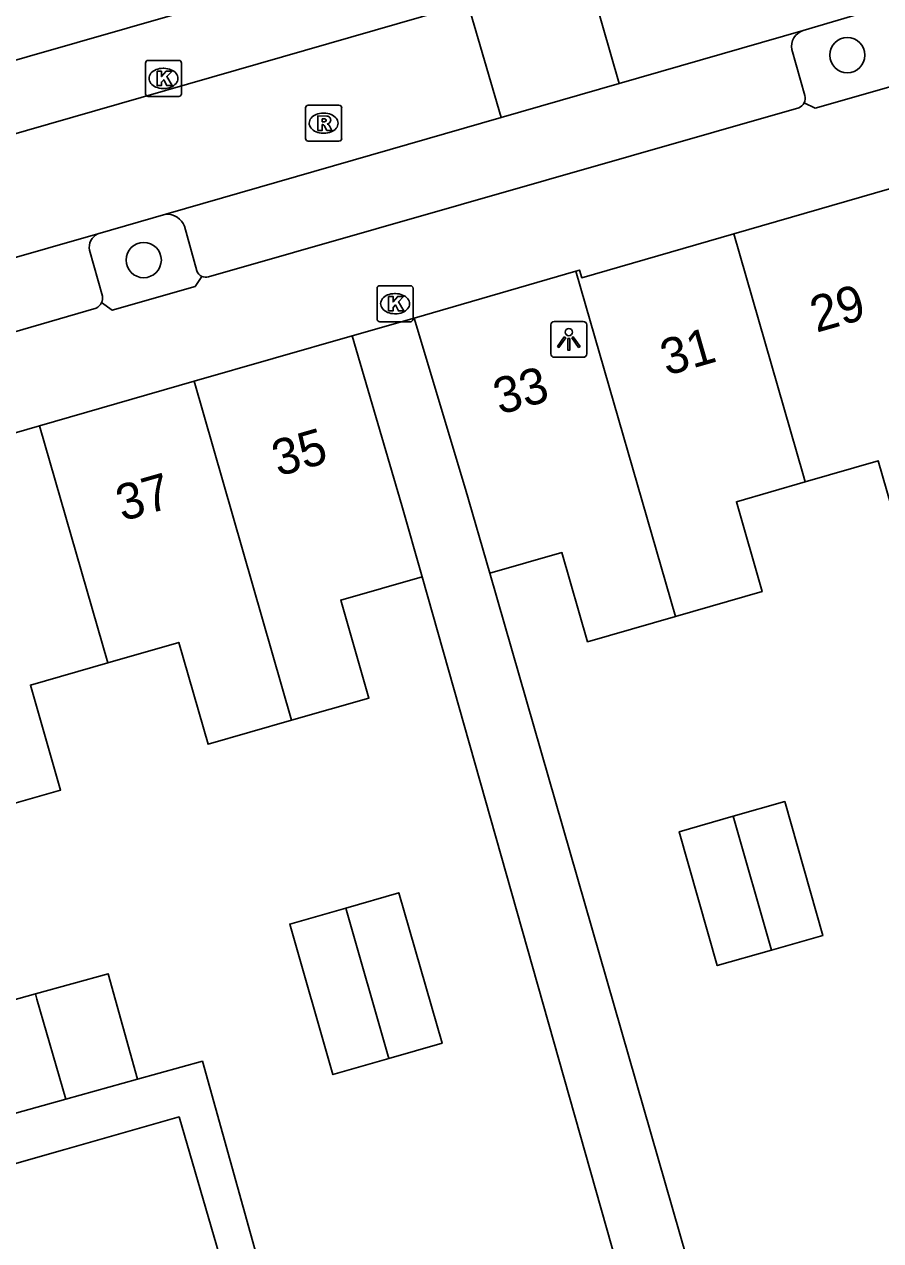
# Model space of a CAD drawing. Extents: x 159718 to 160783, y 383290 to 384030.
# Drawn here: x 160303.99 to 160327.77, y 383562.46 to 383596.25 of the extents above; entities that cross this region are included whole.
import ezdxf

# ---------------------------------------------------------------- set-up
doc = ezdxf.new("R2010")
doc.units = 0
for name, color, linetype in [('IMGEO_Boom', 7, 'Continuous'), ('IMGEO_Kolk', 7, 'Continuous'), ('IMGEO_Lichtpunt', 7, 'Continuous'), ('IMGEO_Pand', 7, 'Continuous'), ('IMGEO_Pand_nummerreeks', 7, 'Continuous'), ('IMGEO_Parkeervlak_open', 7, 'Continuous'), ('IMGEO_Rijbaan_lokaal_open', 7, 'Continuous'), ('IMGEO_Rioolput', 7, 'Continuous'), ('IMGEO_Voetpad_open', 7, 'Continuous')]:
    doc.layers.add(name, color=color, linetype=linetype)

msp = doc.modelspace()

# ---------------------------------------------------------------- linework, layer by layer
at = {"layer": 'IMGEO_Boom'}
for centre in [(160326.846, 383595.394), (160307.303, 383589.7)]:
    msp.add_circle(centre, 0.489, dxfattribs=at)
at = {"layer": 'IMGEO_Kolk'}
for p, q in [((160307.351, 383594.322), (160307.351, 383595.174)), ((160307.426, 383595.248), (160308.278, 383595.248)), ((160307.839, 383595.028), (160307.864, 383595.028)), ((160308.352, 383595.174), (160308.352, 383594.322)), ((160307.862, 383594.468), (160307.837, 383594.468)), ((160308.278, 383594.248), (160307.426, 383594.248)), ((160313.783, 383588.063), (160313.783, 383588.915)), ((160313.858, 383588.989), (160314.71, 383588.989)), ((160314.784, 383588.915), (160314.784, 383588.063)), ((160314.271, 383588.769), (160314.296, 383588.769)), ((160314.71, 383587.989), (160313.858, 383587.989)), ((160314.294, 383588.209), (160314.269, 383588.209))]:
    msp.add_line(p, q, dxfattribs=at)
for points in [[(160307.351, 383594.322), (160307.351, 383595.174)], [(160307.426, 383595.248), (160308.278, 383595.248)], [(160308.352, 383595.174), (160308.352, 383594.322)], [(160307.672, 383594.948), (160307.795, 383594.948), (160307.795, 383594.797), (160307.925, 383594.948), (160308.089, 383594.948), (160307.943, 383594.797), (160308.096, 383594.548), (160307.944, 383594.548), (160307.859, 383594.712), (160307.795, 383594.645), (160307.795, 383594.548), (160307.672, 383594.548), (160307.672, 383594.948)], [(160308.278, 383594.248), (160307.426, 383594.248)], [(160313.783, 383588.063), (160313.783, 383588.915)], [(160313.858, 383588.989), (160314.71, 383588.989)], [(160314.784, 383588.915), (160314.784, 383588.063)], [(160314.104, 383588.689), (160314.227, 383588.689), (160314.227, 383588.538), (160314.357, 383588.689), (160314.521, 383588.689), (160314.375, 383588.538), (160314.528, 383588.289), (160314.376, 383588.289), (160314.291, 383588.453), (160314.227, 383588.386), (160314.227, 383588.289), (160314.104, 383588.289), (160314.104, 383588.689)], [(160314.71, 383587.989), (160313.858, 383587.989)]]:
    msp.add_lwpolyline(points, dxfattribs=at)
for centre, start, end in [((160307.428, 383595.172), 91.552, 178.448), ((160307.428, 383595.172), 91.552, 178.448), ((160308.276, 383595.172), 1.552, 88.448), ((160308.276, 383595.172), 1.552, 88.448), ((160307.428, 383594.324), 181.552, 268.448), ((160307.428, 383594.324), 181.552, 268.448), ((160308.276, 383594.324), 271.552, 358.448), ((160308.276, 383594.324), 271.552, 358.448), ((160313.86, 383588.913), 91.552, 178.448), ((160313.86, 383588.913), 91.552, 178.448), ((160314.708, 383588.913), 1.552, 88.448), ((160314.708, 383588.913), 1.552, 88.448), ((160313.86, 383588.065), 181.552, 268.448), ((160313.86, 383588.065), 181.552, 268.448), ((160314.708, 383588.065), 271.552, 358.448), ((160314.708, 383588.065), 271.552, 358.448)]:
    msp.add_arc(centre, 0.0765, start, end, dxfattribs=at)
for centre, major_axis, ratio, start_param, end_param in [((160307.838, 383594.748), (-0.387, 0.002), 0.722429, 4.712389, 7.853982), ((160307.863, 383594.748), (-0.39, 0.002), 0.717154, 1.570796, 4.712389), ((160314.27, 383588.489), (-0.387, 0.002), 0.722429, 4.712389, 7.853982), ((160314.295, 383588.489), (-0.39, 0.002), 0.717154, 1.570796, 4.712389)]:
    msp.add_ellipse(centre, major_axis=major_axis, ratio=ratio, start_param=start_param, end_param=end_param, dxfattribs=at)
at = {"layer": 'IMGEO_Lichtpunt'}
for p, q in [((160318.61, 383587.902), (160318.61, 383587.095)), ((160318.61, 383587.902), (160318.61, 383587.095)), ((160319.512, 383587.997), (160318.704, 383587.997)), ((160319.512, 383587.997), (160318.704, 383587.997)), ((160319.606, 383587.095), (160319.606, 383587.902)), ((160319.606, 383587.095), (160319.606, 383587.902)), ((160318.704, 383587.001), (160319.512, 383587.001)), ((160318.704, 383587.001), (160319.512, 383587.001))]:
    msp.add_line(p, q, dxfattribs=at)
for points in [[(160318.984, 383587.566), (160319.023, 383587.538), (160318.835, 383587.276), (160318.797, 383587.303), (160318.984, 383587.566)], [(160319.196, 383587.538), (160319.234, 383587.565), (160319.421, 383587.303), (160319.382, 383587.275), (160319.196, 383587.538)], [(160319.086, 383587.518), (160319.133, 383587.518), (160319.133, 383587.196), (160319.086, 383587.196), (160319.086, 383587.518)]]:
    msp.add_lwpolyline(points, dxfattribs=at)
msp.add_circle((160319.109, 383587.7), 0.0994, dxfattribs=at)
for centre, start, end in [((160318.704, 383587.902), 90, 180), ((160318.704, 383587.902), 90, 180), ((160319.512, 383587.902), 0, 90), ((160319.512, 383587.902), 0, 90), ((160318.704, 383587.095), 180, 270), ((160318.704, 383587.095), 180, 270), ((160319.512, 383587.095), 270, 0), ((160319.512, 383587.095), 270, 360)]:
    msp.add_arc(centre, 0.0946, start, end, dxfattribs=at)
at = {"layer": 'IMGEO_Pand'}
for points in [[(160328.012, 383591.677), (160323.69, 383590.429)], [(160323.69, 383590.429), (160319.47, 383589.211), (160319.409, 383589.422), (160319.305, 383589.392)], [(160323.69, 383590.429), (160325.61, 383583.776), (160325.678, 383583.54)], [(160319.305, 383589.392), (160314.818, 383588.09)], [(160322.074, 383579.8), (160319.305, 383589.392)], [(160314.818, 383588.09), (160316.244, 383583.337), (160316.916, 383581)], [(160313.09, 383587.598), (160308.703, 383586.333)], [(160315.034, 383580.904), (160314.474, 383582.881), (160313.09, 383587.598)], [(160308.703, 383586.333), (160304.408, 383585.094)], [(160311.411, 383576.917), (160308.703, 383586.333)], [(160304.408, 383585.094), (160300.113, 383583.856)], [(160304.408, 383585.094), (160306.302, 383578.509)], [(160325.678, 383583.54), (160327.702, 383584.127), (160328.421, 383581.626), (160330.724, 383582.283)], [(160322.074, 383579.8), (160324.479, 383580.492), (160323.762, 383582.985), (160325.678, 383583.54)], [(160316.916, 383581), (160318.916, 383581.576), (160319.629, 383579.097), (160322.074, 383579.8)], [(160311.411, 383576.917), (160313.557, 383577.534), (160312.775, 383580.255), (160315.034, 383580.904)], [(160306.302, 383578.509), (160308.275, 383579.077), (160309.088, 383576.249), (160311.411, 383576.917)], [(160306.302, 383578.509), (160304.155, 383577.892), (160304.993, 383574.978), (160302.844, 383574.36)], [(160324.737, 383570.528), (160326.168, 383570.936), (160325.108, 383574.658), (160323.677, 383574.25)], [(160323.677, 383574.25), (160322.17, 383573.821), (160323.23, 383570.099), (160324.737, 383570.528)], [(160323.677, 383574.25), (160324.737, 383570.528)], [(160314.113, 383567.521), (160315.588, 383567.945), (160314.387, 383572.123), (160312.912, 383571.699)], [(160312.912, 383571.699), (160311.357, 383571.252), (160312.559, 383567.073), (160314.113, 383567.521)], [(160312.912, 383571.699), (160314.113, 383567.521)], [(160307.129, 383566.941), (160306.313, 383569.873), (160304.296, 383569.312)], [(160304.296, 383569.312), (160302.498, 383568.812), (160302.538, 383568.664), (160303.293, 383565.952)], [(160305.137, 383566.386), (160304.338, 383569.166), (160304.296, 383569.312)], [(160305.137, 383566.386), (160307.129, 383566.941)], [(160303.293, 383565.952), (160303.314, 383565.878), (160305.137, 383566.386)]]:
    msp.add_lwpolyline(points, dxfattribs=at)
at = {"layer": 'IMGEO_Parkeervlak_open'}
for points in [[(160360.615, 383611.67), (160327.739, 383602.146), (160280.384, 383588.556), (160278.661, 383588.057)], [(160325.665, 383594.27), (160325.304, 383595.549)], [(160308.437, 383590.644), (160308.776, 383589.4)], [(160306.155, 383588.702), (160305.795, 383589.974)]]:
    msp.add_lwpolyline(points, dxfattribs=at)
for centre, radius, start, end in [((160325.747, 383595.642), 0.453, 106.42, 191.8445), ((160325.407, 383594.188), 0.271, 333.2912, 17.7396), ((160307.924, 383590.417), 0.561, 23.8591, 90.4132), ((160306.206, 383590.051), 0.418, 115.3607, 190.6061), ((160309.024, 383589.487), 0.263, 199.4219, 245.0121), ((160305.822, 383588.659), 0.336, 335.2577, 7.4372)]:
    msp.add_arc(centre, radius, start, end, dxfattribs=at)
at = {"layer": 'IMGEO_Rijbaan_lokaal_open'}
for points in [[(160319.597, 383597.777), (160320.503, 383594.602)], [(160278.849, 383586.224), (160280.889, 383586.747), (160286.571, 383588.273), (160316.301, 383596.829)], [(160316.301, 383596.829), (160317.226, 383593.659)], [(160325.619, 383596.076), (160327.401, 383596.608)], [(160320.503, 383594.602), (160325.619, 383596.076)], [(160320.503, 383594.602), (160317.226, 383593.659)], [(160317.226, 383593.659), (160307.92, 383590.978)], [(160306.027, 383590.429), (160307.92, 383590.978)], [(160288.354, 383585.361), (160306.027, 383590.429)]]:
    msp.add_lwpolyline(points, dxfattribs=at)
at = {"layer": 'IMGEO_Rioolput'}
for p, q in [((160311.874, 383594.004), (160312.726, 383594.004)), ((160311.799, 383593.078), (160311.799, 383593.93)), ((160312.287, 383593.784), (160312.312, 383593.784)), ((160312.8, 383593.93), (160312.8, 383593.078)), ((160312.726, 383593.004), (160311.874, 383593.004)), ((160312.31, 383593.224), (160312.285, 383593.224))]:
    msp.add_line(p, q, dxfattribs=at)
for points in [[(160311.874, 383594.004), (160312.726, 383594.004)], [(160311.799, 383593.078), (160311.799, 383593.93)], [(160312.388, 383593.702), (160312.136, 383593.704), (160312.136, 383593.304)], [(160312.314, 383593.623), (160312.26, 383593.623), (160312.26, 383593.542)], [(160312.8, 383593.93), (160312.8, 383593.078)], [(160312.136, 383593.304), (160312.26, 383593.304), (160312.26, 383593.466), (160312.271, 383593.466)], [(160312.26, 383593.542), (160312.312, 383593.542)], [(160312.318, 383593.437), (160312.389, 383593.304), (160312.529, 383593.304), (160312.464, 383593.43)], [(160312.726, 383593.004), (160311.874, 383593.004)]]:
    msp.add_lwpolyline(points, dxfattribs=at)
for centre, radius, start, end in [((160311.876, 383593.928), 0.0765, 91.552, 178.448), ((160311.876, 383593.928), 0.0765, 91.552, 178.448), ((160312.724, 383593.928), 0.0765, 1.552, 88.448), ((160312.724, 383593.928), 0.0765, 1.552, 88.448), ((160312.32, 383593.527), 0.0964, 77.0061, 93.1865), ((160312.387, 383593.592), 0.109, 350.3612, 89.416), ((160312.27, 383593.413), 0.0533, 26.0293, 88.6989), ((160312.296, 383593.731), 0.19, 274.7715, 282.9687), ((160312.334, 383593.584), 0.0378, 276.6634, 79.6772), ((160312.385, 383593.592), 0.112, 277.5842, 350.9817), ((160312.369, 383593.377), 0.108, 29.5134, 73.7905), ((160311.876, 383593.08), 0.0765, 181.552, 268.448), ((160311.876, 383593.08), 0.0765, 181.552, 268.448), ((160312.724, 383593.08), 0.0765, 271.552, 358.448), ((160312.724, 383593.08), 0.0765, 271.552, 358.448)]:
    msp.add_arc(centre, radius, start, end, dxfattribs=at)
for centre, major_axis, ratio, start_param, end_param in [((160312.286, 383593.504), (-0.387, 0.002), 0.722429, 4.712389, 7.853982), ((160312.311, 383593.504), (-0.39, 0.002), 0.717154, 1.570796, 4.712389)]:
    msp.add_ellipse(centre, major_axis=major_axis, ratio=ratio, start_param=start_param, end_param=end_param, dxfattribs=at)
at = {"layer": 'IMGEO_Voetpad_open'}
for points in [[(160328.421, 383594.852), (160328.255, 383594.576), (160325.953, 383593.92), (160325.649, 383594.066)], [(160309.105, 383589.237), (160325.495, 383593.932)], [(160308.913, 383589.249), (160308.73, 383588.965), (160306.427, 383588.309), (160306.127, 383588.518)], [(160316.916, 383581), (160326.462, 383547.802), (160350.934, 383561.274), (160348.434, 383569.96), (160343.073, 383588.584)], [(160305.982, 383588.363), (160289.61, 383583.608)], [(160314.818, 383588.09), (160313.09, 383587.598)], [(160307.129, 383566.941), (160308.932, 383567.443), (160316.004, 383542.044), (160324.687, 383546.825), (160315.034, 383580.904)], [(160293.768, 383560.15), (160294.999, 383560.501), (160294.575, 383561.992), (160305.113, 383564.993), (160308.287, 383565.897), (160315.335, 383541.676), (160301.026, 383533.81)]]:
    msp.add_lwpolyline(points, dxfattribs=at)
for centre, radius, start, end in [((160325.406, 383594.189), 0.272, 289.0175, 333.0375), ((160309.024, 383589.49), 0.266, 245.1933, 287.654), ((160305.819, 383588.661), 0.34, 298.7236, 335.0947)]:
    msp.add_arc(centre, radius, start, end, dxfattribs=at)

# ---------------------------------------------------------------- texts
at = {"layer": 'IMGEO_Pand_nummerreeks'}
for s, rotation, p in [('29', 16.0485, (160325.986, 383587.679)), ('31', 16.0485, (160321.83, 383586.483)), ('33', 16.0371, (160317.191, 383585.399)), ('35', 16.0485, (160311.04, 383583.682)), ('37', 16.0485, (160306.71, 383582.437))]:
    msp.add_text(s, height=1, rotation=rotation, dxfattribs=at).set_placement(p)

doc.saveas('drawing.dxf')
